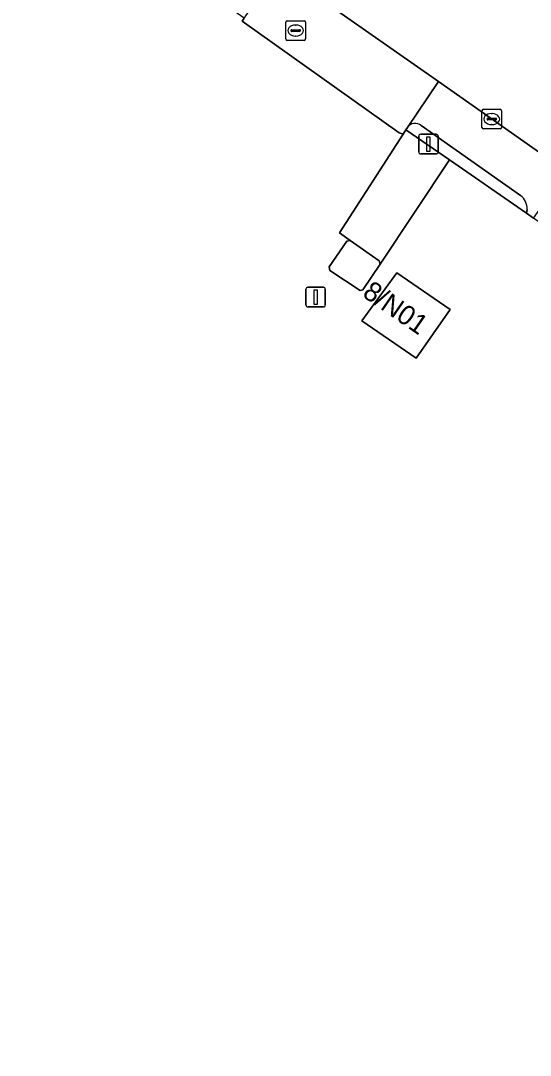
# Model space of a CAD drawing. Extents: x 155018 to 156648, y 383979 to 385733.
# Drawn here: x 155205.2 to 155231.2, y 384867.6 to 384920.3 of the extents above; entities that cross this region are included whole.
import ezdxf

# ---------------------------------------------------------------- set-up
doc = ezdxf.new("R2010")
doc.units = 0
for name, color, linetype in [('IMGEO_Brandkraan', 7, 'Continuous'), ('IMGEO_Erf', 7, 'Continuous'), ('IMGEO_Hek', 7, 'Continuous'), ('IMGEO_Kolk', 7, 'Continuous'), ('IMGEO_Lage_trafo', 7, 'Continuous'), ('IMGEO_Lichtmast', 7, 'Continuous'), ('IMGEO_Pand', 7, 'Continuous'), ('IMGEO_Pand_nummerreeks', 7, 'Continuous'), ('IMGEO_Parkeervlak_open', 7, 'Continuous'), ('IMGEO_Rijbaan_lokaal_gesloten', 7, 'Continuous'), ('IMGEO_Rijbaan_lokaal_open', 7, 'Continuous'), ('IMGEO_Voetpad_open', 7, 'Continuous')]:
    doc.layers.add(name, color=color, linetype=linetype)

msp = doc.modelspace()

# ---------------------------------------------------------------- linework, layer by layer
at = {"layer": 'IMGEO_Brandkraan'}
for p, q in [((155218.71, 384919.324), (155218.71, 384920.176)), ((155218.785, 384920.25), (155219.637, 384920.25)), ((155219.012, 384919.793), (155219.41, 384919.793)), ((155219.198, 384920.03), (155219.223, 384920.03)), ((155219.711, 384920.176), (155219.711, 384919.324)), ((155219.637, 384919.25), (155218.785, 384919.25)), ((155218.969, 384919.744), (155218.969, 384919.756)), ((155219.407, 384919.707), (155219.009, 384919.707)), ((155219.221, 384919.47), (155219.196, 384919.47)), ((155219.453, 384919.756), (155219.453, 384919.744))]:
    msp.add_line(p, q, dxfattribs=at)
for points in [[(155218.71, 384919.324), (155218.71, 384920.176)], [(155218.785, 384920.25), (155219.637, 384920.25)], [(155219.711, 384920.176), (155219.711, 384919.324)], [(155219.637, 384919.25), (155218.785, 384919.25)]]:
    msp.add_lwpolyline(points, dxfattribs=at)
for centre, radius, start, end in [((155218.787, 384920.174), 0.0765, 91.552, 178.448), ((155218.787, 384920.174), 0.0765, 91.552, 178.448), ((155219.009, 384919.753), 0.0403, 85.8775, 175.7526), ((155219.414, 384919.755), 0.0386, 1.7309, 96.639), ((155219.635, 384920.174), 0.0765, 1.552, 88.448), ((155219.635, 384920.174), 0.0765, 1.552, 88.448), ((155218.787, 384919.326), 0.0765, 181.552, 268.448), ((155218.787, 384919.326), 0.0765, 181.552, 268.448), ((155219.006, 384919.743), 0.0366, 178.938, 274.7102), ((155219.41, 384919.75), 0.043, 264.8664, 352.4533), ((155219.635, 384919.326), 0.0765, 271.552, 358.448), ((155219.635, 384919.326), 0.0765, 271.552, 358.448)]:
    msp.add_arc(centre, radius, start, end, dxfattribs=at)
for centre, major_axis, ratio, start_param, end_param in [((155219.197, 384919.75), (-0.387, 0.002), 0.722429, 4.712389, 7.853982), ((155219.222, 384919.75), (-0.39, 0.002), 0.717154, 1.570796, 4.712389)]:
    msp.add_ellipse(centre, major_axis=major_axis, ratio=ratio, start_param=start_param, end_param=end_param, dxfattribs=at)
at = {"layer": 'IMGEO_Erf'}
msp.add_lwpolyline([(155335.262, 384837.311), (155330.905, 384840.366), (155281.186, 384875.226), (155281.002, 384875.356), (155276.212, 384878.76), (155276.077, 384878.856), (155237.974, 384905.505), (155237.774, 384905.646), (155231.318, 384910.204), (155230.963, 384910.455), (155227.038, 384913.165), (155223.513, 384907.874), (155222.624, 384906.563), (155222.485, 384906.531), (155220.945, 384907.552), (155220.914, 384907.73), (155221.818, 384909.034), (155221.988, 384909.066), (155221.443, 384909.464), (155224.676, 384914.482), (155224.481, 384914.547), (155216.482, 384920.228), (155216.589, 384920.387), (155102.876, 385000)], dxfattribs=at)
msp.add_lwpolyline([(155227.07, 384905.56), (155225.34, 384903.08), (155222.58, 384904.99), (155224.36, 384907.42)], close=True, dxfattribs=at)
at = {"layer": 'IMGEO_Hek'}
msp.add_lwpolyline([(155224.481, 384914.547), (155216.482, 384920.228)], dxfattribs=at)
at = {"layer": 'IMGEO_Kolk'}
for p, q in [((155228.691, 384914.82), (155228.691, 384915.672)), ((155228.766, 384915.746), (155229.618, 384915.746)), ((155229.692, 384915.672), (155229.692, 384914.82)), ((155228.95, 384915.24), (155228.95, 384915.252)), ((155229.388, 384915.203), (155228.99, 384915.203)), ((155228.993, 384915.289), (155229.391, 384915.289)), ((155229.179, 384915.526), (155229.204, 384915.526)), ((155229.434, 384915.252), (155229.434, 384915.24)), ((155229.618, 384914.746), (155228.766, 384914.746)), ((155229.202, 384914.966), (155229.177, 384914.966))]:
    msp.add_line(p, q, dxfattribs=at)
for points in [[(155228.691, 384914.82), (155228.691, 384915.672)], [(155228.766, 384915.746), (155229.618, 384915.746)], [(155229.692, 384915.672), (155229.692, 384914.82)], [(155229.618, 384914.746), (155228.766, 384914.746)]]:
    msp.add_lwpolyline(points, dxfattribs=at)
for centre, radius, start, end in [((155228.768, 384915.67), 0.0765, 91.552, 178.448), ((155228.768, 384915.67), 0.0765, 91.552, 178.448), ((155229.616, 384915.67), 0.0765, 1.552, 88.448), ((155229.616, 384915.67), 0.0765, 1.552, 88.448), ((155228.99, 384915.249), 0.0403, 85.8775, 175.7526), ((155228.987, 384915.239), 0.0366, 178.938, 274.7102), ((155229.391, 384915.246), 0.043, 264.8664, 352.4533), ((155229.395, 384915.251), 0.0386, 1.7309, 96.639), ((155228.768, 384914.822), 0.0765, 181.552, 268.448), ((155228.768, 384914.822), 0.0765, 181.552, 268.448), ((155229.616, 384914.822), 0.0765, 271.552, 358.448), ((155229.616, 384914.822), 0.0765, 271.552, 358.448)]:
    msp.add_arc(centre, radius, start, end, dxfattribs=at)
for centre, major_axis, ratio, start_param, end_param in [((155229.178, 384915.246), (-0.387, 0.002), 0.722429, 4.712389, 7.853982), ((155229.203, 384915.246), (-0.39, 0.002), 0.717154, 1.570796, 4.712389)]:
    msp.add_ellipse(centre, major_axis=major_axis, ratio=ratio, start_param=start_param, end_param=end_param, dxfattribs=at)
at = {"layer": 'IMGEO_Lage_trafo'}
msp.add_lwpolyline([(155221.988, 384909.066), (155221.818, 384909.034), (155220.914, 384907.73), (155220.945, 384907.552), (155222.485, 384906.531), (155222.624, 384906.563), (155223.513, 384907.874), (155223.465, 384908.038)], close=True, dxfattribs=at)
at = {"layer": 'IMGEO_Lichtmast'}
for p, q in [((155225.472, 384913.576), (155225.472, 384914.376)), ((155225.472, 384914.376), (155225.472, 384913.576)), ((155225.572, 384914.476), (155226.362, 384914.476)), ((155226.362, 384914.476), (155225.572, 384914.476)), ((155226.462, 384914.376), (155226.462, 384913.576)), ((155226.462, 384913.576), (155226.462, 384914.376)), ((155226.362, 384913.476), (155225.572, 384913.476)), ((155225.572, 384913.476), (155226.362, 384913.476)), ((155219.829, 384906.69), (155220.619, 384906.69)), ((155220.619, 384906.69), (155219.829, 384906.69)), ((155219.729, 384905.79), (155219.729, 384906.59)), ((155219.729, 384906.59), (155219.729, 384905.79)), ((155220.719, 384906.59), (155220.719, 384905.79)), ((155220.719, 384905.79), (155220.719, 384906.59)), ((155220.619, 384905.69), (155219.829, 384905.69)), ((155219.829, 384905.69), (155220.619, 384905.69))]:
    msp.add_line(p, q, dxfattribs=at)
for points in [[(155225.892, 384914.351), (155226.042, 384914.351), (155226.042, 384913.601), (155225.892, 384913.601), (155225.892, 384914.351)], [(155220.149, 384906.565), (155220.299, 384906.565), (155220.299, 384905.815), (155220.149, 384905.815), (155220.149, 384906.565)]]:
    msp.add_lwpolyline(points, dxfattribs=at)
for centre, start, end in [((155225.572, 384914.376), 90, 180), ((155225.572, 384914.376), 90, 180), ((155226.362, 384914.376), 0, 90), ((155226.362, 384914.376), 360, 90), ((155225.572, 384913.576), 180, 270), ((155225.572, 384913.576), 180, 270), ((155226.362, 384913.576), 270, 0), ((155226.362, 384913.576), 270, 0), ((155219.829, 384906.59), 90, 180), ((155219.829, 384906.59), 90, 180), ((155220.619, 384906.59), 0, 90), ((155220.619, 384906.59), 360, 90), ((155219.829, 384905.79), 180, 270), ((155219.829, 384905.79), 180, 270), ((155220.619, 384905.79), 270, 0), ((155220.619, 384905.79), 270, 0)]:
    msp.add_arc(centre, 0.1, start, end, dxfattribs=at)
at = {"layer": 'IMGEO_Pand'}
msp.add_lwpolyline([(155225.34, 384903.08), (155227.07, 384905.56), (155224.36, 384907.42), (155222.58, 384904.99)], close=True, dxfattribs=at)
at = {"layer": 'IMGEO_Parkeervlak_open'}
for points in [[(155226.479, 384917.152), (155224.895, 384914.817)], [(155230.985, 384910.654), (155230.963, 384910.455), (155231.318, 384910.204), (155232.999, 384912.577), (155226.479, 384917.152)], [(155225.597, 384914.916), (155230.658, 384911.362)]]:
    msp.add_lwpolyline(points, dxfattribs=at)
for centre, radius, start, end in [((155225.291, 384914.545), 0.481, 50.5038, 145.5506), ((155230.165, 384910.705), 0.821, 356.4526, 53.1285)]:
    msp.add_arc(centre, radius, start, end, dxfattribs=at)
at = {"layer": 'IMGEO_Rijbaan_lokaal_gesloten'}
msp.add_lwpolyline([(155200.809, 384935.124), (155218.313, 384922.864), (155226.479, 384917.152), (155232.999, 384912.577), (155239.472, 384908.041), (155277.864, 384881.141), (155282.705, 384877.749), (155304.661, 384862.364), (155312.349, 384857.014), (155325.715, 384847.641), (155332.492, 384842.858), (155336.825, 384839.821), (155356.019, 384826.372), (155356.562, 384825.996), (155363.162, 384821.376)], dxfattribs=at)
at = {"layer": 'IMGEO_Rijbaan_lokaal_open'}
msp.add_lwpolyline([(155218.313, 384922.864), (155216.663, 384920.497), (155216.589, 384920.387), (155216.482, 384920.228), (155224.481, 384914.547), (155224.676, 384914.482), (155224.817, 384914.699), (155224.895, 384914.817), (155226.479, 384917.152)], close=True, dxfattribs=at)
at = {"layer": 'IMGEO_Voetpad_open'}
msp.add_lwpolyline([(155224.817, 384914.699), (155224.676, 384914.482), (155221.443, 384909.464), (155221.988, 384909.066), (155223.465, 384908.038), (155223.513, 384907.874), (155227.038, 384913.165)], close=True, dxfattribs=at)
for points in [[(155224.895, 384914.817), (155224.817, 384914.699), (155227.038, 384913.165), (155230.963, 384910.455), (155230.985, 384910.654)], [(155230.658, 384911.362), (155225.597, 384914.916)]]:
    msp.add_lwpolyline(points, dxfattribs=at)
for centre, radius, start, end in [((155225.291, 384914.545), 0.481, 50.5038, 145.5506), ((155230.165, 384910.705), 0.821, 356.4526, 53.1285)]:
    msp.add_arc(centre, radius, start, end, dxfattribs=at)

# ---------------------------------------------------------------- texts
at = {"layer": 'IMGEO_Pand_nummerreeks'}
msp.add_text('8/N01', height=1, rotation=325.3327, dxfattribs=at).set_placement((155222.553, 384906.257))

doc.saveas('drawing.dxf')
